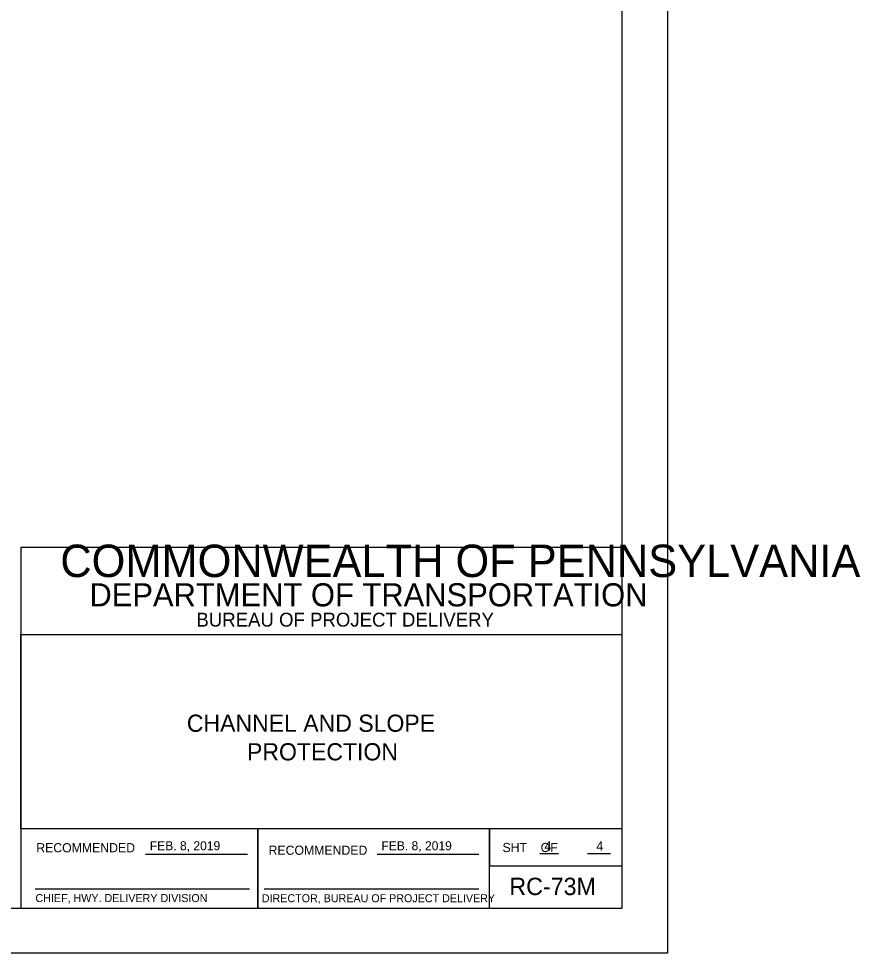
# Model space of a CAD drawing. Extents: x 636462 to 638208, y 299350 to 300538.
# Drawn here: x 637928.2 to 638208, y 299350.4 to 299661.3 of the extents above; entities that cross this region are included whole.
import ezdxf

# ---------------------------------------------------------------- set-up
doc = ezdxf.new("R2010")
doc.units = 0
for name, color, linetype in [('1', 7, 'Continuous'), ('Default', 7, 'Continuous'), ('PLT-BNDY', 7, 'Continuous')]:
    doc.layers.add(name, color=color, linetype=linetype)

msp = doc.modelspace()

# ---------------------------------------------------------------- linework, layer by layer
at = {"layer": '1'}
for p, q in [((637970.38, 299383.44), (638004.27, 299383.44)), ((638047.38, 299383.44), (638081.25, 299383.44)), ((638101.54, 299383.66), (638107.68, 299383.66)), ((638117.35, 299383.66), (638124.99, 299383.66)), ((637933.68, 299371.87), (638004.93, 299371.87)), ((637933.68, 299371.87), (638004.93, 299371.87)), ((638009.85, 299371.87), (638081.19, 299371.87)), ((638009.85, 299371.87), (638081.19, 299371.87))]:
    msp.add_line(p, q, dxfattribs=at)
msp.add_lwpolyline([(638128.91, 299365.45), (638128.91, 299929.45), (637342.91, 299929.45), (637342.91, 299365.45), (638128.91, 299365.45), (638128.91, 299391.81), (637928.91, 299391.81), (637928.91, 299456.49), (638128.91, 299456.49), (638128.91, 299485.45), (637928.91, 299485.45), (637928.91, 299365.45), (638007.72, 299365.45), (638007.72, 299391.81), (638007.72, 299365.45), (638084.72, 299365.45), (638084.72, 299391.81), (638084.72, 299379.49), (638128.91, 299379.49)], dxfattribs=at)
at = {"layer": 'PLT-BNDY'}
msp.add_lwpolyline([(637302.91, 299944.45), (638143.91, 299944.45), (638143.91, 299350.45), (637302.91, 299350.45)], close=True, dxfattribs=at)

# ---------------------------------------------------------------- texts
at = {"layer": '1'}
for s, height, p in [('COMMONWEALTH OF PENNSYLVANIA', 10.7834, (637942.07, 299475.59)), ('DEPARTMENT OF TRANSPORTATION', 7.6843, (637951.75, 299465.84)), ('BUREAU OF PROJECT DELIVERY', 4.6221, (637987.32, 299459.11)), ('FEB. 8, 2019', 3, (637971.82, 299384.72)), ('FEB. 8, 2019', 3, (638048.82, 299384.72)), ('4', 3.13, (638103.05, 299384.54)), ('4', 3.13, (638120.28, 299384.59)), ('RECOMMENDED', 3.048, (637934.08, 299384.04)), ('RECOMMENDED', 3.048, (638011.32, 299383.21)), ('SHT    OF', 3.048, (638089.08, 299384.12)), ('APPROVED', 0.0192, (637971.94, 299383.38)), ('APPROVED', 0.0192, (637971.94, 299383.38)), ('APPROVED', 0.0192, (637971.94, 299383.38)), ('APPROVED', 0.0192, (637971.94, 299383.38)), ('APPROVED', 0.0192, (637971.94, 299383.38)), ('APPROVED', 0.0192, (637971.94, 299383.38)), ('APPROVED', 0.0192, (637971.94, 299383.38)), ('APPROVED', 0.0192, (637971.94, 299383.38)), ('APPROVED', 0.0192, (637971.94, 299383.38)), ('APPROVED', 0.0192, (637971.94, 299383.38)), ('APPROVED', 0.0192, (637971.94, 299383.38)), ('APPROVED', 0.0192, (637971.94, 299383.38)), ('CHIEF, HWY. DELIVERY DIVISION', 2.6623, (637933.82, 299367.49)), ('CHIEF, HWY. DELIVERY DIVISION', 2.6623, (637933.82, 299367.49)), ('DIRECTOR, BUREAU OF PROJECT DELIVERY', 2.6623, (638009.07, 299367.43)), ('DIRECTOR, BUREAU OF PROJECT DELIVERY', 2.6623, (638009.07, 299367.43))]:
    msp.add_text(s, height=height, dxfattribs=at).set_placement(p)
at = {"layer": 'Default'}
for s, height, p in [('CHANNEL AND SLOPE', 5.7257, (637984.13, 299424.12)), ('PROTECTION', 5.726, (638004.14, 299414.61)), ('RC-73M', 5.779, (638091.37, 299369.81))]:
    msp.add_text(s, height=height, dxfattribs=at).set_placement(p)

doc.saveas('drawing.dxf')
